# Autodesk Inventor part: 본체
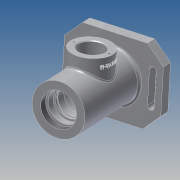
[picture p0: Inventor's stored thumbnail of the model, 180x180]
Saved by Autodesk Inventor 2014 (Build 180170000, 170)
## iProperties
Created: 2017-10
Part Number: 본체
Material: 알루미늄 6061
Document SubType Name: Modeling
Designer: kb543-05
Mass: 790 g
Surface Area: 664.656 cm^2
Volume: 291.584 cm^3
Density: 2.70934 g/cm^3
Appearance: 알루미늄 - 평지
Author: kb543-05
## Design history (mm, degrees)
sketch "스케치2"
  geometry: L1 (0, 0)-(31, 0); L2 (31, 0)-(31, -99); L3 (31, -99)-(0, -99); L4 (0, -99)-(0, 0)
  constraints: 8 end point, 2 parallel, 1 horizontal, 1 perpendicular
  dimensions: "d1" = 99 distance of L1.end L2.end; "d2" = 62 diameter of L2 L4
revolve "회전1" sketch "스케치2" stored, may be unused: angle "d3" = 90 deg
sketch "스케치3"
  geometry: L1 (-58, 47)-(58, 47); L2 (58, 47)-(58, -47); L3 (58, -47)-(-58, -47); L4 (-58, -47)-(-58, 47); L5 (-87.549, 0)-(134.549, 0); L6 (0, 69.118)-(0, -96.765); L7 (-46, 20)-(-46, -20); L8 (-50, 20)-(-50, -20); L9 (-42, -20)-(-42, 20); L10 (46, 20)-(46, -20); L11 (42, 20)-(42, -20); L12 (50, -20)-(50, 20); C1 r 31 at (0, 0) reference; C2 r 31 at (0, 0); A1 r 4 centre (-46, 20) between (-42, 20) and (-50, 20); A2 r 4 centre (-46, -20) between (-50, -20) and (-42, -20); A3 r 4 centre (46, 20) between (50, 20) and (42, 20); A4 r 4 centre (46, -20) between (42, -20) and (50, -20); 5 further points
  constraints: 28 end point, 8 point on circle, 8 tangent, 7 parallel, 5 centre point, 5 midpoint, 3 horizontal alignment, 3 perpendicular, 2 equal radius, 2 point on line, 1 coincident, 1 horizontal, 1 vertical alignment
  dimensions: "d4" = 94 distance of L1.end L2.end; "d5" = 116 distance of L1.start L1.end; "d6" = 40 distance of L7.start L7.end; "d7" = 46 distance between parallel lines of L7 L6; "d8" = 4 radius of A1; "d9" = 92 distance between parallel lines of L7 L10
extrude "돌출1" join sketch "스케치3" distance "d10" = 13; taper "d11" = 0 deg
chamfer "모따기1" distance "d12" = 20; stored, may be unused: second distance "d13" = 2, angle "d14" = 45 deg
sketch "스케치4"
  geometry: C1 r 35 at (0, 0); 1 further point
  constraints: 1 centre point, 1 coincident
  dimensions: "d15" = 70 diameter of C1
extrude "돌출2" join sketch "스케치4" distance "d16" = 3; taper "d17" = 0 deg
sketch "스케치5"
  geometry: L1 (-31, -99)-(31, -99) reference; L2 (-31, 0)-(31, 0) reference; L3 (47, -112)-(27, -112) reference; L4 (27, -112)-(27, -99) reference; L5 (27, -99)-(47, -99) reference; L6 (47, -99)-(47, -112) reference; L7 (-35, -115)-(35, -115) reference; L8 (35, -112)-(-35, -112) reference; L9 (20, -99)-(-20, -99) reference; L10 (20, -99)-(20, -112) reference; L11 (-20, -112)-(20, -112) reference; L12 (-20, -99)-(-20, -112) reference; L13 (-35, -112)-(-47, -112) reference; L14 (-47, -112)-(-47, -99) reference; L15 (-47, -99)-(-31, -99) reference; L16 (-31, -99)-(-31, 0) reference; L17 (-31, 0)-(31, 0) reference; L18 (31, 0)-(31, -99) reference; L19 (0, 0)-(21, 0); L20 (21, 0)-(21, -9); L21 (21, -9)-(0, -9); L22 (0, -9)-(0, 0); L23 (0, -9)-(24, -9); L24 (24, -9)-(24, -12); L25 (24, -12)-(0, -12); L26 (0, -12)-(0, -9); L27 (0, -12)-(20, -12); L28 (20, -12)-(20, -21); L29 (20, -21)-(0, -21); L30 (0, -21)-(0, -12); L31 (0, -21)-(17.5, -21); L32 (17.5, -21)-(17.5, -37); L33 (17.5, -37)-(0, -37); L34 (0, -37)-(0, -21); L35 (0, -24.25)-(18.5, -24.25); L36 (18.5, -24.25)-(18.5, -26); L37 (18.5, -26)-(0, -26); L38 (0, -26)-(0, -24.25); L39 (0, -37)-(26, -37); L40 (26, -37)-(26, -75); L41 (26, -75)-(0, -75); L42 (0, -75)-(0, -37); L43 (0, -75)-(17.5, -75); L44 (17.5, -75)-(17.5, -86); L45 (17.5, -86)-(0, -86); L46 (0, -86)-(0, -75); L47 (0, -86)-(16.5, -86); L48 (16.5, -86)-(16.5, -91); L49 (16.5, -91)-(0, -91); L50 (0, -91)-(0, -86); L51 (0, -91)-(10, -91); L52 (10, -91)-(10, -93.7); L53 (10, -93.7)-(0, -93.7); L54 (0, -93.7)-(0, -91); L55 (0, -93.7)-(12.5, -93.7); L56 (12.5, -93.7)-(12.5, -101); L57 (12.5, -101)-(0, -101); L58 (0, -101)-(0, -93.7); L59 (0, -115)-(22, -115); L60 (22, -115)-(16, -101); L61 (16, -101)-(0, -101); L62 (0, -101)-(0, -115); L63 (31, -99)-(47, -99) reference; L64 (47, -99)-(47, -112) reference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
  constraints: 96 end point, 21 parallel, 13 perpendicular, 10 horizontal, 4 collinear, 4 point on line
  dimensions: "d19" = 12 distance between parallel lines of L25 L2; "d20" = 3 distance of L23.end L24.end; "d21" = 21 distance between parallel lines of L19 L29; "d22" = 26 distance between parallel lines of L37 L2; "d23" = 38 distance between parallel lines of L41 L39; "d24" = 60 distance between parallel lines of L45 L37; "d25" = 11 distance between parallel lines of L33 L37; "d26" = 1.75 distance between parallel lines of L37 L35; "d27" = 5 distance between parallel lines of L49 L45; "d29" = 7.3 distance of L55.end L56.end; "d30" = 44 diameter of L59.end L62; "d31" = 32 diameter of L60.end L62; "d32" = 25 diameter of L56 L58; "d34" = 14 distance of L61.end L59.start; "d35" = 2.7 distance between parallel lines of L53 L49; "d36" = 42 diameter of L20 L22; "d37" = 48 diameter of L24 L26; "d38" = 40 diameter of L28 L30; "d39" = 35 diameter of L32 L34; "d40" = 37 diameter of L36 L38; "d41" = 52 diameter of L40 L42; "d42" = 35 diameter of L44 L46; "d43" = 33 diameter of L48 L50; "d44" = 20 diameter of L52 L54; "d45" = 11 distance between parallel lines of L41 L45 (derived); "d46" = 30 deg angle of L56 L69; "d47" = 0.7 distance between parallel lines of L68 L61
  node "투영된 루프1"
  node "투영된 루프2"
  node "투영된 루프3"
  node "투영된 루프4"
  node "절단 모서리 투영1"
revolve "회전2" stored, may be unused: angle "d48" = 90 deg
feature "스레드1" dims "d49" = 10, "d50" = 0
sketch "스케치6"
  geometry: L1 (-58, -99)-(-50, -99) reference; L2 (-50, -99)-(-50, -112) reference; L3 (-50, -112)-(-58, -112) reference; L4 (-58, -112)-(-58, -99) reference; L5 (-42, -99)-(-31, -99) reference; L6 (-31, -99)-(-31, 0) reference; L7 (-31, 0)-(-21, 0) reference; L8 (-21, 0)-(-21, -9) reference; L9 (-21, -9)-(-24, -9) reference; L10 (-24, -9)-(-24, -12) reference; L11 (-24, -12)-(-20, -12) reference; L12 (-20, -12)-(-20, -21) reference; L13 (-20, -21)-(-17.5, -21) reference; L14 (-17.5, -21)-(-17.5, -24.25) reference; L15 (-17.5, -24.25)-(-18.5, -24.25) reference; L16 (-18.5, -24.25)-(-18.5, -26) reference; L17 (-18.5, -26)-(-17.5, -26) reference; L18 (-17.5, -26)-(-17.5, -37) reference; L19 (-17.5, -37)-(-26, -37) reference; L20 (-26, -37)-(-26, -75) reference; L21 (-26, -75)-(-17.5, -75) reference; L22 (-17.5, -75)-(-17.5, -86) reference; L23 (-17.5, -86)-(-16.5, -86) reference; L24 (-16.5, -86)-(-16.5, -91) reference; L25 (-16.5, -91)-(-10, -91) reference; L26 (-10, -91)-(-10, -93.7) reference; L27 (-10, -93.7)-(-12.5, -93.7) reference; L28 (-12.5, -93.7)-(-12.5, -100.3) reference; L29 (-12.904, -101)-(-16, -101) reference; L30 (-16, -101)-(-22, -115) reference; L31 (-22, -115)-(-35, -115) reference; L32 (-35, -115)-(-35, -112) reference; L33 (-35, -112)-(-42, -112) reference; L34 (-42, -112)-(-42, -99) reference; L35 (31, -99)-(42, -99) reference; L36 (42, -99)-(42, -112) reference; L37 (42, -112)-(35, -112) reference; L38 (35, -112)-(35, -115) reference; L39 (35, -115)-(22, -115) reference; L40 (22, -115)-(16, -101) reference; L41 (16, -101)-(12.904, -101) reference; L42 (12.5, -100.3)-(12.5, -93.7) reference; L43 (12.5, -93.7)-(10, -93.7) reference; L44 (10, -93.7)-(10, -91) reference; L45 (10, -91)-(16.5, -91) reference; L46 (16.5, -91)-(16.5, -86) reference; L47 (16.5, -86)-(17.5, -86) reference; L48 (17.5, -86)-(17.5, -75) reference; L49 (17.5, -75)-(26, -75) reference; L50 (26, -75)-(26, -37) reference; L51 (26, -37)-(17.5, -37) reference; L52 (17.5, -37)-(17.5, -26) reference; L53 (17.5, -26)-(18.5, -26) reference; L54 (18.5, -26)-(18.5, -24.25) reference; L55 (18.5, -24.25)-(17.5, -24.25) reference; L56 (17.5, -24.25)-(17.5, -21) reference; L57 (17.5, -21)-(20, -21) reference; L58 (20, -21)-(20, -12) reference; L59 (20, -12)-(24, -12) reference; L60 (24, -12)-(24, -9) reference; L61 (24, -9)-(21, -9) reference; L62 (21, -9)-(21, 0) reference; L63 (21, 0)-(31, 0) reference; L64 (31, 0)-(31, -99) reference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; C1 r 25 at (0, -56)
  constraints: 4 end point, 3 midpoint, 1 centre point, 1 perpendicular, 1 point on line
  dimensions: "d52" = 50 diameter of C1
  node "절단 모서리 투영2"
node "작업 평면1"
sketch "스케치7"
  geometry: L1 (0, 0)-(0, -139); L2 (-69, -56)-(82, -56); L3 (-31, 0)-(31, 0) reference; C1 r 25 at (0, -56)
  constraints: 4 end point, 2 point on line, 1 centre point, 1 perpendicular, 1 vertical
  dimensions: "d54" = 56 distance between parallel lines of L2 L3; "d55" = 50 diameter of C1
extrude "돌출3" join sketch "스케치7" stored distance "d56" = 3; taper "d57" = 0 deg
sketch "스케치8"
  geometry: C1 r 25 at (0, 0) reference; C2 r 16 at (0, 0); 1 further point
  constraints: 1 centre point, 1 coincident
  dimensions: "d58" = 32 diameter of C2
extrude "돌출4" cut sketch "스케치8" stored distance "d59" = 3; taper "d60" = 0 deg
sketch "스케치9"
  geometry: C1 r 25 at (0, 0) reference; A1 r 20.5 centre (0, 0) between (20.5, 0) and (-20.5, 0); 1 further point
  constraints: 2 point on circle, 1 centre point, 1 coincident
  dimensions: "d61" = 41 diameter of A1
hole "구멍1" sketch "스케치9" at (20.5, 0), (-20.5, 0) diameter "d62" = 2.459; stored, may be unused: countersink angle "d66" = 82 deg, drill point angle "d68" = 118 deg; dims "d63" = 6, "d64" = 3.023, "d65" = 2, "d67" = 8
chamfer "모따기2" distance "d69" = 1; stored, may be unused: second distance "d70" = 2, angle "d71" = 45 deg
fillet "모깎기1" dims "d72" = 0.3
fillet "모깎기2" dims "d73" = 3
fillet "모깎기3" dims "d74" = 3
node "작업 평면2"
sketch "스케치10"
  geometry: L1 (0, 25)-(0, -25) reference; L2 (-78, 56)-(-16, 56) reference; 2 further points
  constraints: 1 other
  dimensions: "d75" = 10 distance from line of point (-10, 0) L1; "d76" = 56 distance from line of L2 point (-10, 0)
feature "엠보싱1" sketch "스케치10" dims "d1" = 99, "d2" = 62, "d77" = 0.5, "d78" = 0
fillet "모깎기4" dims "d79" = 3
node "솔리드1"
other parameters: "d53" = 47
